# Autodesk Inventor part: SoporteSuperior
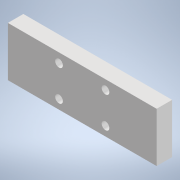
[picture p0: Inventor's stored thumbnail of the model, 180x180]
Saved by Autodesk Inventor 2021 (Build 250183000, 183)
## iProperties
Created: 2021-02
Part Number: SoporteSuperior
Material: Genérico
Document SubType Name: Modeling
Designer: ATOUZA
Density: 1 g/cm^3
Appearance: Valor por defecto
Author: ATOUZA
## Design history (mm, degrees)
sketch "Boceto1"
  geometry: L1 (-48, -16)-(48, -16); L2 (48, -16)-(48, 16); L3 (48, 16)-(-48, 16); L4 (-48, 16)-(-48, -16); L5 (-48, -16)-(48, 16); L6 (48, -16)-(-48, 16); L7 (-48, 0)-(48, 0); L8 (0, 16)-(0, -16); C1 r 2.5 at (-15, 10); C2 r 2.5 at (-15, -10); C3 r 2.5 at (15, 10); C4 r 2.5 at (15, -10); 1 further point
  constraints: 16 end point, 6 midpoint, 4 centre point, 3 symmetric about line, 2 parallel, 1 horizontal, 1 perpendicular, 3 other
  dimensions: "d0" = 96 distance of L3.end L2.end; "d1" = 32 distance of L2.end L1.end; "d2" = 5 diameter of C1; "d4" = 15 distance from line of L8 C1.centre; "d5" = 10 distance from line of L7 C1.centre
extrude "Extrusión1" new body sketch "Boceto1" distance "d6" = 10; taper "d7" = 0 deg
node "Sólido1"
